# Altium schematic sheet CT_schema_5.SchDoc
size 298 x 247 mm
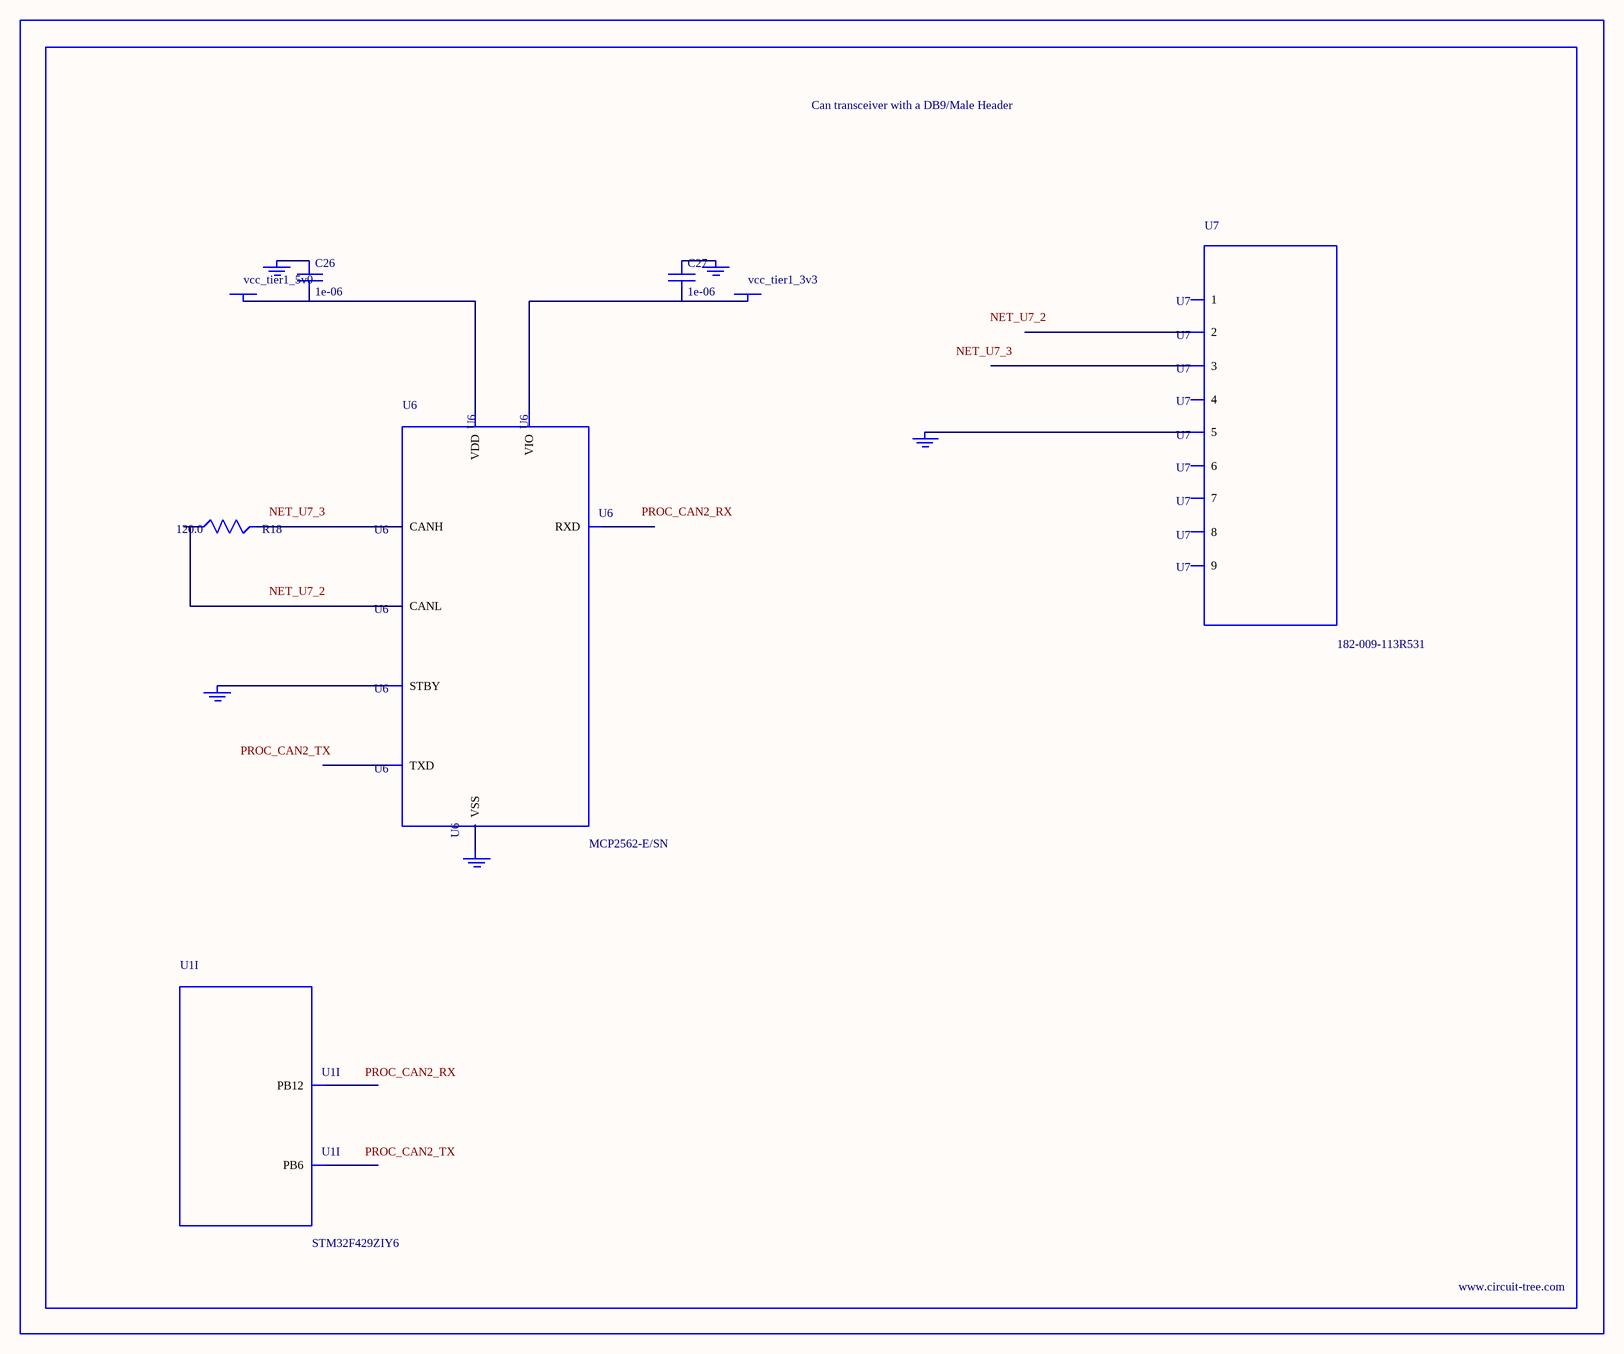
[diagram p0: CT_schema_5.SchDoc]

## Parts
BORDER4  (no value)
C26  1e-06  [C0603]
C27  1e-06  [C0603]
GND_INSTANCE_4_0  (no value)
GND_INSTANCE_4_1  (no value)
GND_INSTANCE_4_2  (no value)
GND_INSTANCE_4_3  (no value)
GND_INSTANCE_4_4  (no value)
POWER_INSTANCE_4_0  vcc_tier1_5v0
POWER_INSTANCE_4_1  vcc_tier1_3v3
R18  120.0  [R0603]
U1  STM32F429ZIY6  [WLCSP143]  (part I of 13)
U6  MCP2562-E/SN  [SOIC-8]
U7  182-009-113R531  [182-009-MALE]

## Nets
NetC26_1: C26.1 GND_INSTANCE_4_0.0(GND)
NetC26_2: C26.2 POWER_INSTANCE_4_0.0(PWR) U6.3(VDD)
NetC27_1: C27.1 GND_INSTANCE_4_1.0(GND)
NetC27_2: C27.2 POWER_INSTANCE_4_1.0(PWR) U6.5(VIO)
NetGND_INSTANCE_4_2_0: GND_INSTANCE_4_2.0(GND) U6.8(STBY)
NetGND_INSTANCE_4_3_0: GND_INSTANCE_4_3.0(GND) U6.2(VSS)
NetGND_INSTANCE_4_4_0: GND_INSTANCE_4_4.0(GND) U7.5
NetR18_1: R18.1 U6.6(CANL)
NetR18_2: R18.2 U6.7(CANH)

Not connected (* = marked no-connect by the designer): U1 A8(PB6) M2(PB12); U6 1(TXD) 4(RXD); U7 1 2 3 4 6 7 8 9

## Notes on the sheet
- Labels drawn without touching a wire or pin: NET_U7_2, NET_U7_3, PROC_CAN2_RX, PROC_CAN2_TX

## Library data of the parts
BORDER4 = BORDER_PAGE4
C26 C27 = C0603C105K3RACTU
GND_INSTANCE_4_0-GND_INSTANCE_4_4 = GND
POWER_INSTANCE_4_0 POWER_INSTANCE_4_1 = PWR
R18 = RC0603JR-07120RL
